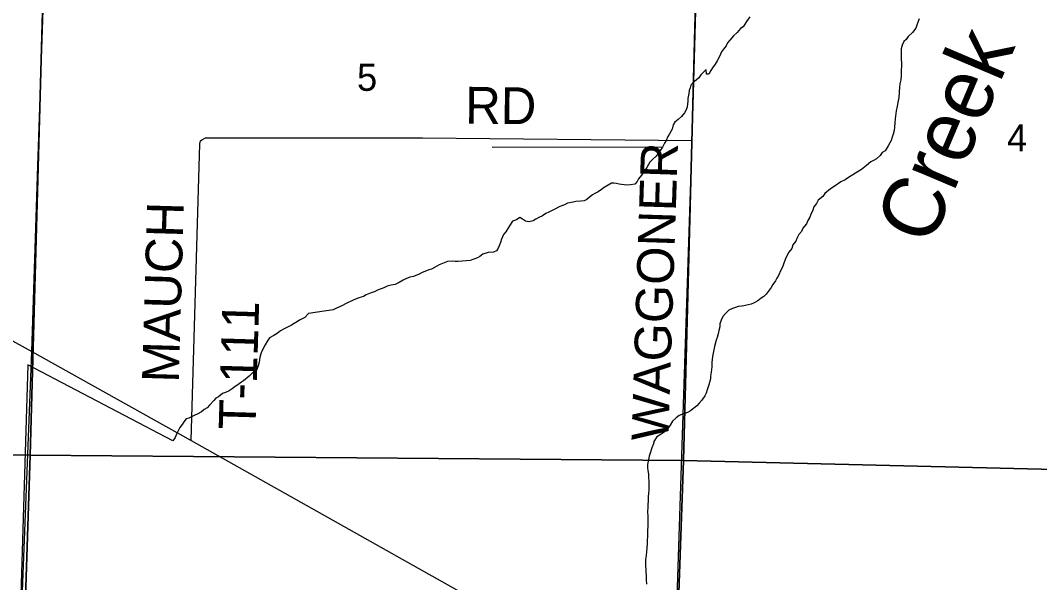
# Model space of a CAD drawing. Extents: x 1588073 to 2013523, y 1090242 to 1357120.
# Drawn here: x 1754621 to 1762930, y 1243614 to 1248194 of the extents above; entities that cross this region are included whole.
import ezdxf

# ---------------------------------------------------------------- set-up
doc = ezdxf.new("R2010")
doc.units = 0
for name, color, linetype in [('GM_X_County_Road', 7, 'Continuous'), ('GM_X_County_Road_Text', 7, 'Continuous'), ('GM_X_Minor_River', 7, 'Continuous'), ('GM_X_Minor_River_Text', 7, 'Continuous'), ('GM_X_Section', 7, 'Continuous'), ('GM_X_Section_Text', 7, 'Continuous'), ('GM_X_Township_Road', 7, 'Continuous'), ('GM_X_Township_Road_Text', 7, 'Continuous'), ('GM_X_US_Route', 7, 'Continuous')]:
    doc.layers.add(name, color=color, linetype=linetype)

msp = doc.modelspace()

# ---------------------------------------------------------------- linework, layer by layer
at = {"layer": 'GM_X_County_Road'}
msp.add_lwpolyline([(1759945.6, 1242581.8), (1760098.6, 1247214.7), (1760179.2, 1250093), (1760141.3, 1250222), (1760107.6, 1252739.2), (1760060.4, 1256704.3), (1760069.3, 1257059.2), (1760068.5, 1257195.5)], dxfattribs=at)
at = {"layer": 'GM_X_Minor_River'}
for p, q in [((1759855, 1247159.8), (1758468.4, 1247158.4)), ((1754681.7, 1245388.5), (1754574.9, 1241971)), ((1755864.1, 1244767.8), (1754681.7, 1245388.5))]:
    msp.add_line(p, q, dxfattribs=at)
for points in [[(1760566.7, 1248223.9), (1760540.3, 1248186.1), (1760513.8, 1248142.3), (1760491.6, 1248126.5), (1760463.3, 1248094.7), (1760435, 1248066.9), (1760404.6, 1248033.2), (1760386.4, 1248011.3), (1760376.1, 1247987.4), (1760353.8, 1247959.5), (1760337.6, 1247937.7), (1760329.3, 1247917.7), (1760315, 1247889.8), (1760302.8, 1247863.8), (1760284.5, 1247836), (1760264.2, 1247806.1), (1760249.9, 1247786.2), (1760233.6, 1247756.3), (1760213.6, 1247754.5), (1760212, 1247794.6), (1760169.5, 1247751), (1760151.2, 1247727.1), (1760129, 1247707.3), (1760108.8, 1247689.5), (1760086.6, 1247665.6), (1760080.3, 1247645.7), (1760074.1, 1247621.7), (1760069.8, 1247597.7), (1760063.4, 1247557.6), (1760061.2, 1247533.6), (1760059, 1247513.6)], [(1761949.5, 1248205.7), (1761935.1, 1248171.8), (1761920.7, 1248131.8), (1761894.3, 1248096), (1761858, 1248062.3), (1761843.7, 1248038.4), (1761823.5, 1248022.6), (1761809.2, 1247992.7), (1761802.9, 1247962.7), (1761802, 1247882.5), (1761803.6, 1247838.4), (1761802.9, 1247772.3), (1761800.6, 1247744.2), (1761798.3, 1247710.2), (1761789.9, 1247676.2), (1761787.6, 1247650.1), (1761782.8, 1247566), (1761774.3, 1247526), (1761770, 1247496), (1761761.6, 1247458), (1761755.2, 1247414), (1761752.9, 1247391.9), (1761750.6, 1247359.9), (1761748.2, 1247323.8), (1761745.9, 1247297.8), (1761735.6, 1247265.8), (1761729.4, 1247243.8), (1761721.1, 1247215.9), (1761708.9, 1247195.9), (1761694.6, 1247172.1), (1761670.2, 1247132.2), (1761648, 1247116.4), (1761629.7, 1247092.5), (1761599.4, 1247066.8), (1761575.3, 1247053), (1761553.1, 1247041.2), (1761518.8, 1247011.5), (1761478.4, 1246977.8), (1761430.1, 1246948.3), (1761371.7, 1246914.8), (1761345.5, 1246895), (1761309.3, 1246877.4), (1761262.9, 1246845.8), (1761226.6, 1246822.1), (1761178.2, 1246782.5), (1761161.9, 1246758.6), (1761125.6, 1246728.9), (1761111.3, 1246701), (1761089, 1246675.2), (1761082.7, 1246647.2), (1761064.4, 1246613.3), (1761058.1, 1246591.3), (1761039.8, 1246563.4), (1761029.5, 1246535.5), (1760999.1, 1246501.7), (1760988.8, 1246473.8), (1760968.6, 1246449.9), (1760950.2, 1246416), (1760944, 1246394.1), (1760919.7, 1246364.2), (1760909.3, 1246334.3), (1760887, 1246306.4), (1760864.6, 1246264.6), (1760854.3, 1246238.6), (1760846.1, 1246214.7), (1760833.7, 1246182.7), (1760819.5, 1246158.8), (1760801, 1246116.9), (1760788.8, 1246095)], [(1760059, 1247513.6), (1760056.7, 1247487.6), (1760046.4, 1247459.6), (1760034.2, 1247439.7), (1760009.9, 1247409.9), (1759983.6, 1247386.1), (1759955.3, 1247364.3), (1759943.1, 1247342.4), (1759934.7, 1247308.4), (1759912.3, 1247270.6), (1759900.1, 1247248.6), (1759885.8, 1247216.7), (1759871.5, 1247192.8), (1759857.2, 1247160.9), (1759836.9, 1247133), (1759816.6, 1247107.2), (1759804.4, 1247087.3), (1759774.1, 1247061.5), (1759753.8, 1247039.7), (1759741.6, 1247019.8), (1759727.4, 1246995.9), (1759705, 1246960), (1759684.7, 1246932.2), (1759660.4, 1246904.3), (1759648.1, 1246882.4), (1759629.9, 1246858.6), (1759593.8, 1246852.9), (1759561.7, 1246851.2), (1759501.8, 1246859.9), (1759481.8, 1246864.1), (1759459.8, 1246868.3), (1759439.8, 1246866.5), (1759413.6, 1246852.8), (1759381.4, 1246833.1), (1759359.2, 1246815.2), (1759331, 1246797.5), (1759304.8, 1246783.7), (1759284.7, 1246771.9), (1759260.5, 1246754.1), (1759240.3, 1246734.3), (1759216.2, 1246724.5), (1759190.1, 1246720.8), (1759150.1, 1246717.2), (1759128, 1246713.4), (1759081.9, 1246703.8), (1759057.7, 1246692.1), (1759017.5, 1246676.4), (1758973.3, 1246652.8), (1758929, 1246631.3), (1758904.9, 1246619.5), (1758876.7, 1246601.7), (1758846.5, 1246588), (1758822.3, 1246574.2), (1758802.2, 1246560.4), (1758766.1, 1246552.8), (1758738.1, 1246559.1), (1758714.3, 1246575.3), (1758692.4, 1246587.6), (1758664.2, 1246569.8), (1758632, 1246558.1), (1758609.6, 1246520.3), (1758579.1, 1246470.5), (1758558.8, 1246448.7), (1758542.5, 1246412.8), (1758534.2, 1246384.8), (1758523.9, 1246356.8), (1758515.6, 1246336.9), (1758501.4, 1246317), (1758477.3, 1246305.2), (1758435.2, 1246301.6), (1758391.1, 1246290), (1758366.8, 1246270.2), (1758346.7, 1246258.4), (1758286.5, 1246237), (1758190.3, 1246230), (1758164.3, 1246230.2), (1758140.3, 1246232.5), (1758104.2, 1246228.8), (1758035.9, 1246201.5), (1757997.7, 1246181.8), (1757973.5, 1246168.1), (1757951.4, 1246162.3), (1757917.3, 1246148.6), (1757895.2, 1246140.8), (1757873, 1246127), (1757824.8, 1246107.4), (1757796.7, 1246101.7), (1757762.5, 1246088.1), (1757740.4, 1246076.2), (1757710.2, 1246058.5), (1757676, 1246042.8), (1757643.9, 1246037.2), (1757609.8, 1246027.5), (1757583.7, 1246015.7), (1757533.4, 1245996.2), (1757513.3, 1245986.4), (1757481.2, 1245974.7), (1757439, 1245959.1), (1757418.8, 1245945.3), (1757380.7, 1245933.6), (1757334.4, 1245914.1)], [(1760788.8, 1246095), (1760776.5, 1246071.1), (1760756.2, 1246041.2), (1760741.9, 1246017.3), (1760725.7, 1245995.4), (1760701.3, 1245963.6), (1760681.1, 1245943.8), (1760661, 1245929.9), (1760632.7, 1245908.2), (1760602.5, 1245892.5), (1760578.4, 1245880.7), (1760554.3, 1245876.9), (1760520.2, 1245867.3), (1760500.2, 1245865.5), (1760472.1, 1245861.7), (1760452, 1245855.9), (1760427.9, 1245846.2), (1760395.8, 1245834.5), (1760369.5, 1245806.7), (1760347.2, 1245780.8), (1760332.9, 1245752.9), (1760324.6, 1245720.9), (1760322.3, 1245696.9), (1760314, 1245666.9), (1760309.7, 1245640.9), (1760301.4, 1245610.9), (1760293.2, 1245589), (1760278.6, 1245537), (1760274.3, 1245509), (1760268.1, 1245483), (1760263.8, 1245457), (1760257.3, 1245406.9), (1760256.9, 1245370.9), (1760252.4, 1245326.8), (1760248.1, 1245296.8), (1760245.9, 1245272.8), (1760233.4, 1245224.8), (1760220.9, 1245182.8), (1760212.6, 1245156.9), (1760200.4, 1245134.9), (1760176, 1245099.1), (1760153.7, 1245075.3), (1760135.5, 1245053.4), (1760107.3, 1245031.7), (1760085.1, 1245013.9), (1760058.9, 1244998.1), (1760038.8, 1244992.3), (1760012.7, 1244984.5), (1759992.6, 1244974.7), (1759968.4, 1244954.9), (1759938.1, 1244929.2), (1759919.7, 1244897.3), (1759899.4, 1244869.4), (1759877.2, 1244845.6), (1759844.9, 1244823.9), (1759810.7, 1244800.2), (1759784.3, 1244764.4), (1759782.1, 1244744.4), (1759767.7, 1244710.4), (1759755.3, 1244668.5), (1759747, 1244644.5), (1759738.6, 1244602.5), (1759734.3, 1244576.5), (1759734, 1244548.4), (1759735.8, 1244526.4), (1759741.5, 1244496.2), (1759741.2, 1244476.2), (1759744.8, 1244432.1), (1759744.1, 1244367.9), (1759741.8, 1244339.9), (1759739.6, 1244315.9), (1759739.2, 1244283.8), (1759736.9, 1244247.8), (1759736.6, 1244225.7), (1759734.3, 1244193.7), (1759735.9, 1244149.6), (1759735.3, 1244093.4), (1759737, 1244071.4), (1759734.7, 1244041.3), (1759732.2, 1243991.2), (1759729.8, 1243955.2), (1759729.6, 1243935.1), (1759727.2, 1243895.1), (1759724.9, 1243867.1), (1759722.6, 1243835), (1759718.2, 1243801), (1759717.8, 1243760.9), (1759719.3, 1243708.8), (1759722.8, 1243662.6), (1759722.6, 1243638.6), (1759724.2, 1243600.5)], [(1757334.4, 1245914.1), (1757276.1, 1245886.6), (1757241.9, 1245868.9), (1757221.8, 1245859.1), (1757193.6, 1245847.4), (1757169.5, 1245835.6), (1756971, 1245805.6), (1756940.7, 1245773.8), (1756902.5, 1245754.2), (1756852.1, 1245724.6), (1756829.9, 1245710.8), (1756799.8, 1245695.1), (1756771.6, 1245681.3), (1756741.4, 1245663.6), (1756713.2, 1245641.8), (1756687, 1245628.1), (1756652.7, 1245606.4), (1756634.5, 1245582.5), (1756616.1, 1245550.6), (1756599.8, 1245520.8), (1756583.4, 1245484.8), (1756573.1, 1245448.9), (1756566.6, 1245408.8), (1756558.3, 1245380.9), (1756548, 1245350.9), (1756521.8, 1245331.1), (1756485.4, 1245295.4), (1756439, 1245257.8), (1756414.8, 1245242), (1756394.6, 1245226.2), (1756370.5, 1245212.4), (1756348.2, 1245192.6), (1756322.1, 1245176.8), (1756291.9, 1245163.1), (1756269.8, 1245153.3), (1756235.5, 1245127.6), (1756215.3, 1245115.8), (1756197.1, 1245095.9), (1756162.7, 1245058.2), (1756142.5, 1245036.4), (1756120.3, 1245022.6), (1756098.1, 1245004.8), (1756061.9, 1244985.1), (1756041.8, 1244977.3), (1755993.5, 1244953.7), (1755971.4, 1244947.9), (1755953.2, 1244924.1), (1755938.9, 1244902.2), (1755920.7, 1244878.3), (1755910.4, 1244856.4), (1755894.1, 1244822.5), (1755883.8, 1244796.5), (1755864.1, 1244767.8)]]:
    msp.add_lwpolyline(points, dxfattribs=at)
at = {"layer": 'GM_X_Section'}
for points in [[(1749184.2, 1250111.8), (1754851.5, 1250122.9), (1754700.3, 1244653.1), (1749045.5, 1244692)], [(1754851.5, 1250122.9), (1760172.3, 1250103), (1760026.9, 1244607.2), (1754700.3, 1244653.1)], [(1760172.3, 1250103), (1765422.5, 1250038.6), (1765498.5, 1250038), (1765302.4, 1244480.3), (1760026.9, 1244607.2)], [(1749045.5, 1244692), (1754700.3, 1244653.1), (1754526.5, 1239347.7), (1748859.5, 1239350.7)], [(1754700.3, 1244653.1), (1760026.9, 1244607.2), (1759839.1, 1239305.9), (1754526.5, 1239347.7)], [(1760026.9, 1244607.2), (1765302.4, 1244480.3), (1765142.6, 1239224.6), (1759839.1, 1239305.9)]]:
    msp.add_lwpolyline(points, close=True, dxfattribs=at)
at = {"layer": 'GM_X_Township_Road'}
for points in [[(1754712.8, 1245495.6), (1754762.2, 1247008.3), (1754808.9, 1248357.1), (1754854.2, 1250090.9), (1754807.7, 1250304.3), (1754813.3, 1250637), (1754814.2, 1252237.3), (1754817, 1252758.6), (1754829.2, 1256686.6)], [(1756013.5, 1244772.3), (1756083.9, 1247188.9), (1756088.3, 1247212.9), (1756100.5, 1247220.7), (1756130.8, 1247236.3), (1757898.5, 1247237.1), (1760098.6, 1247214.7)], [(1754577.8, 1242010.1), (1754577.8, 1242010.1), (1754712.8, 1245495.6)]]:
    msp.add_lwpolyline(points, dxfattribs=at)
at = {"layer": 'GM_X_US_Route'}
msp.add_lwpolyline([(1749415, 1248436.4), (1751954.3, 1247015.3), (1754712.8, 1245495.6), (1756013.5, 1244772.3), (1758628.7, 1243303.4), (1759945.6, 1242581.8), (1761250, 1241834.4), (1763463.4, 1240552.9), (1763789.1, 1240364.4), (1764133.5, 1240165), (1764467.6, 1239971.6), (1764522, 1239940.1)], dxfattribs=at)

# ---------------------------------------------------------------- texts
at = {"layer": 'GM_X_County_Road_Text'}
msp.add_text('WAGGONER', height=300, rotation=88.11408, dxfattribs=at).set_placement((1759902.5, 1244765.2))
at = {"layer": 'GM_X_Minor_River_Text'}
msp.add_text('Creek', height=500.33, rotation=67.04423, dxfattribs=at).set_placement((1762039.4, 1246340.7))
at = {"layer": 'GM_X_Section_Text'}
for s, p in [('5', (1757365.1, 1247620)), ('4', (1762664.9, 1247126.1))]:
    msp.add_text(s, height=221, rotation=0.00001, dxfattribs=at).set_placement(p)
at = {"layer": 'GM_X_Township_Road_Text'}
for s, rotation, p in [('RD', 359.41734, (1758246.2, 1247353.2)), ('MAUCH', 88.33723, (1755911.6, 1245240)), ('T-111', 88.31515, (1756537, 1244856.1))]:
    msp.add_text(s, height=300, rotation=rotation, dxfattribs=at).set_placement(p)

doc.saveas('drawing.dxf')
